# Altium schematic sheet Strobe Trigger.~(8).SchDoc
size B; Organization: Monterey Bay Aquarium Research Institute; Address1: 7700 Sandholdt Rd; Address2: Moss Landing, CA 95039-9644; CompanyName: MBARI
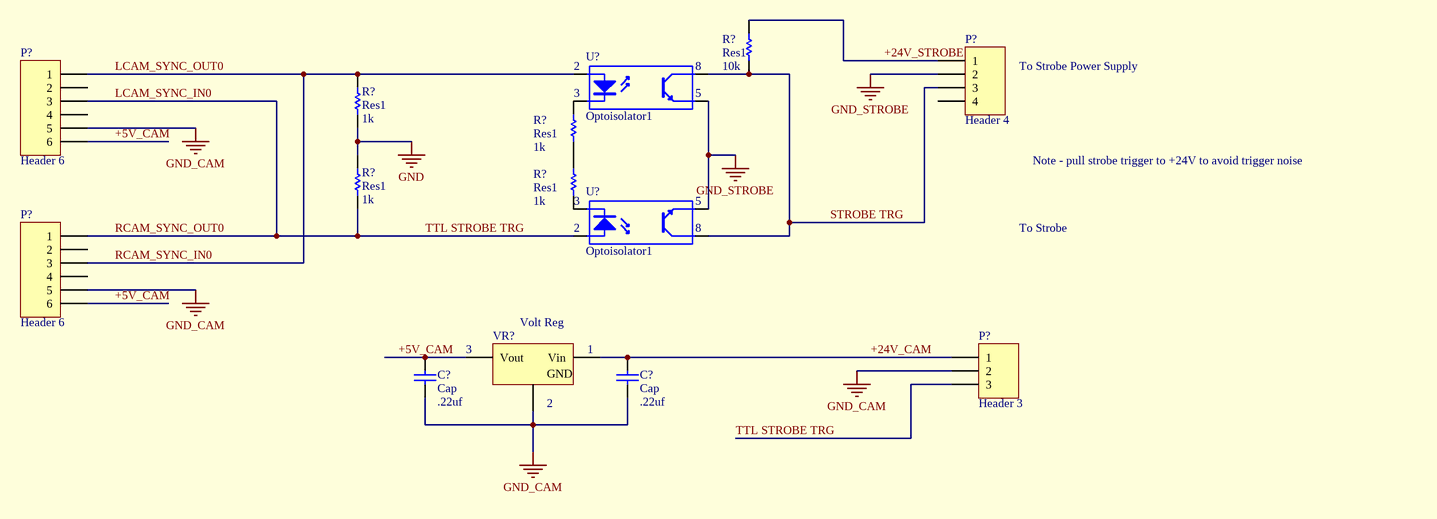
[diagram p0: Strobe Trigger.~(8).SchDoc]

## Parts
(Parts that share a designator on the sheet are numbered #1, #2 ... from top to bottom, then left to right.)
C?#1  Cap  value .22uf  [RAD-0.3]
C?#2  Cap  value .22uf  [RAD-0.3]
P?#1  Header 4  [HDR1X4]
P?#2  Header 6  [HDR1X6]
P?#3  Header 6  [HDR1X6]
P?#4  Header 3  [HDR1X3]
R?#1  Res1  value 10k  [AXIAL-0.3]
R?#2  Res1  value 1k  [AXIAL-0.3]
R?#3  Res1  value 1k  [AXIAL-0.3]
R?#4  Res1  value 1k  [AXIAL-0.3]
R?#5  Res1  value 1k  [AXIAL-0.3]
U?#1  Optoisolator1  [DIP-4]
U?#2  Optoisolator1  [DIP-4]
VR?  Volt Reg  [D2PAK_N]

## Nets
GND: R?#2.1 R?#4.2
GND_CAM: C?#1.1 C?#2.1 P?#2.5 P?#3.5 P?#4.2 VR?.2(GND)
GND_STROBE: P?#1.2 U?#1.3(E) U?#2.3(E)
+5V_CAM: C?#1.2 P?#2.6 P?#3.6 VR?.3(Vout)
+24V_CAM: C?#2.2 P?#4.1 VR?.1(Vin)
+24V_STROBE: P?#1.1 R?#1.2
LCAM_SYNC_IN0: P?#2.3 P?#3.1 P?#4.3 R?#4.1 U?#2.1(A)  [also labelled RCAM_SYNC_OUT0, TTL STROBE TRG]
LCAM_SYNC_OUT0: P?#2.1 P?#3.3 R?#2.2 U?#1.1(A)  [also labelled RCAM_SYNC_IN0]
STROBE TRG: P?#1.3 R?#1.1 U?#1.4(C) U?#2.4(C)
NetR?#3_1: R?#3.1 R?#5.2
NetR?#3_2: R?#3.2 U?#1.2(K)
NetR?#5_1: R?#5.1 U?#2.2(K)

Not connected (* = marked no-connect by the designer): P?#1 4; P?#2 2 4; P?#3 2 4

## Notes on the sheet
- (near U?#1) 2
- 3
- (near U?#1) 8
- (near U?#1) 5
- To Strobe Power Supply
- Note - pull strobe trigger to +24V to avoid trigger noise
- (near U?#2) 2
- (near R?#5) 3
- (near U?#2) 8
- (near U?#2) 5
- To Strobe
- (near VR?) 3
- (near VR?) 1
- (near VR?) 2

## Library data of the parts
C?#1 C?#2 = Cap: Capacitor
P?#1 = Header 4: Header, 4-Pin
P?#2 P?#3 = Header 6: Header, 6-Pin
P?#4 = Header 3: Header, 3-Pin
R?#1-R?#5 = Res1: Resistor
U?#1 U?#2 = Optoisolator1: 4-Pin Phototransistor Optocoupler
VR? = Volt Reg: Voltage Regulator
